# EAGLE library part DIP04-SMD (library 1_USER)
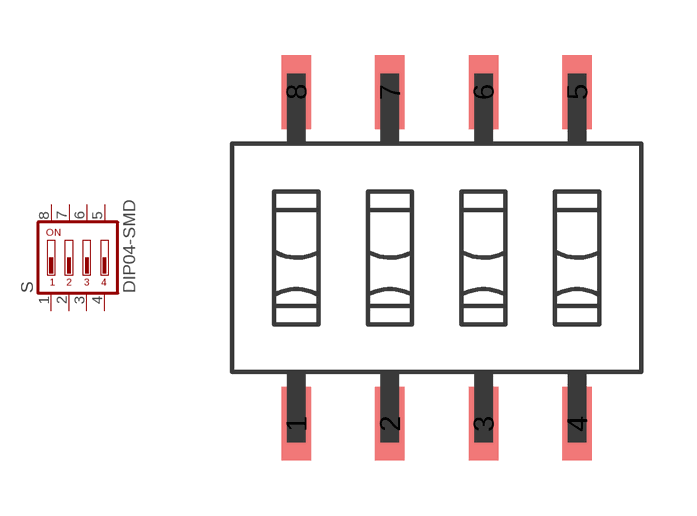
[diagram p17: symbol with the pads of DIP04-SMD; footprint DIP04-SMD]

Designator prefix S

## DIP04-SMD  [DIP04-SMD]
1  1  pas
2  2  pas
3  3  pas
4  4  pas
5  5  pas
6  6  pas
7  7  pas
8  8  pas

## Footprint DIP04-SMD (pad centres in mm)
smd 0.8 x 2: 1 -3.81,-4.5; 2 -1.27,-4.5; 3 1.27,-4.5; 4 3.81,-4.5; 5 3.81,4.5; 6 1.27,4.5; 7 -1.27,4.5; 8 -3.81,4.5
